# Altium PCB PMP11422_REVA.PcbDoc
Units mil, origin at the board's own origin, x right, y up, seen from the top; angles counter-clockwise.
Board outline 3100 x 1500 mil, 4 copper layers (Top Layer, Mid-Layer 1, Mid-Layer 2, Bottom Layer), stack 62 mil thick; 66 components, 31 nets, 197 pads, 23 vias.
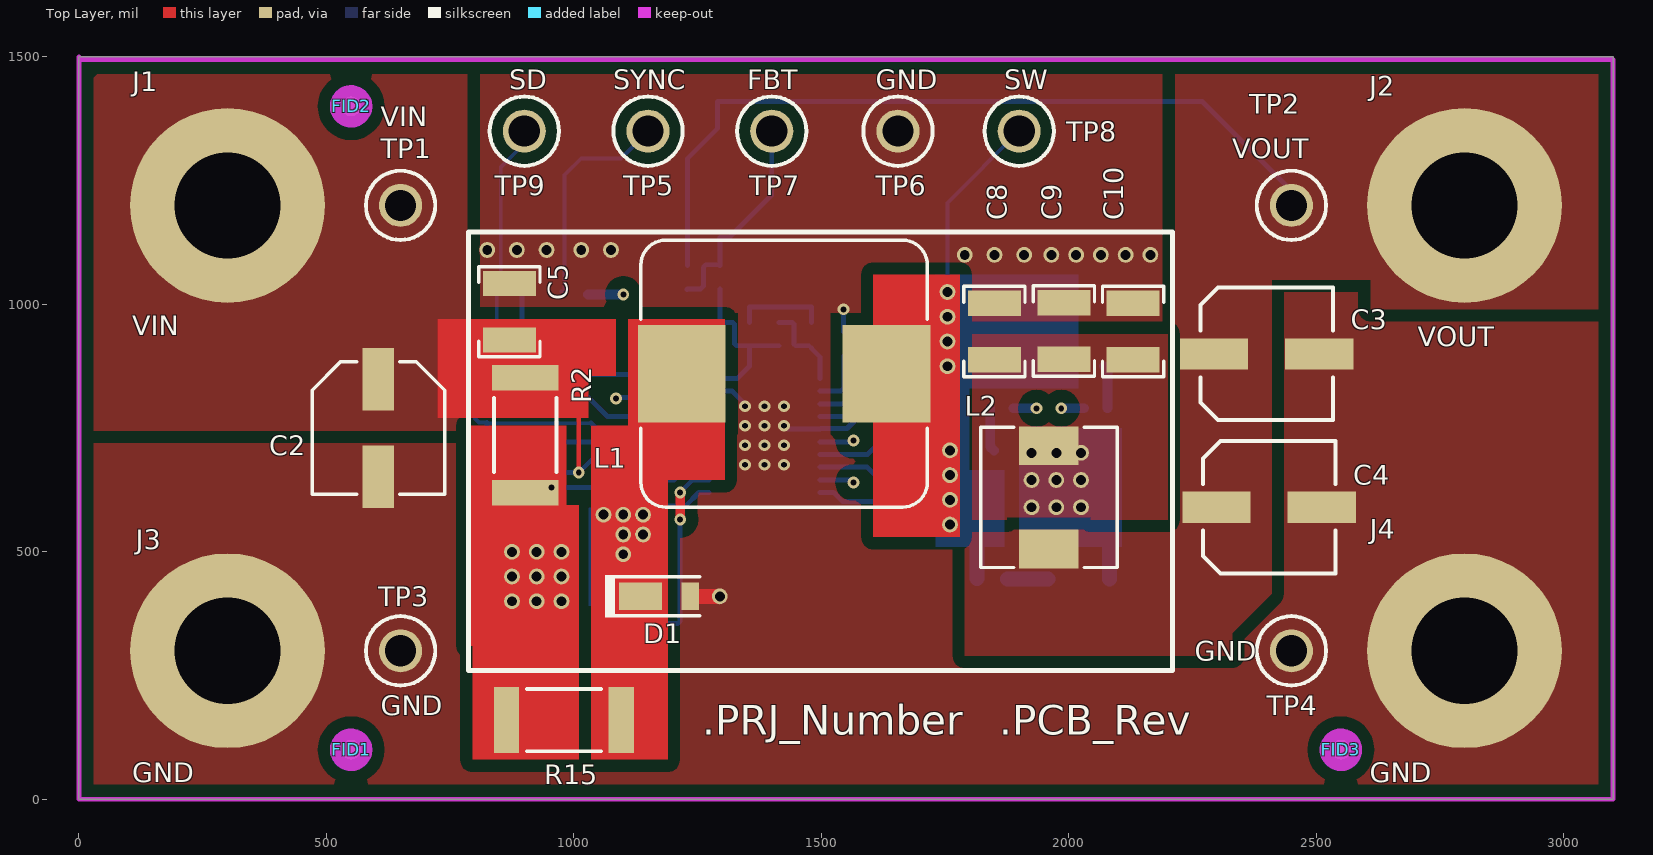
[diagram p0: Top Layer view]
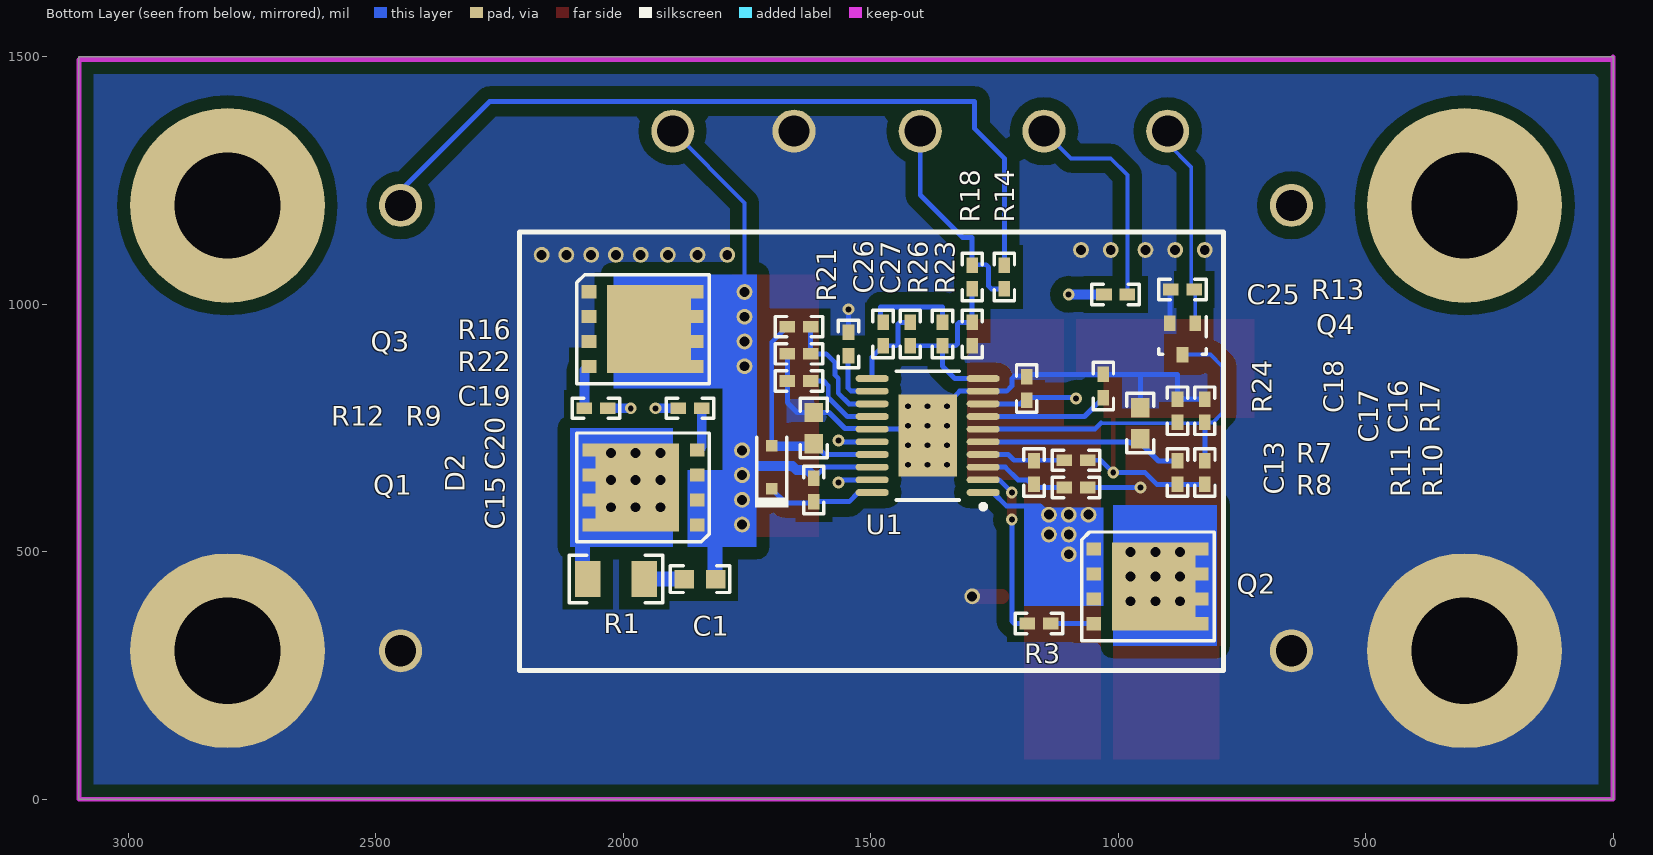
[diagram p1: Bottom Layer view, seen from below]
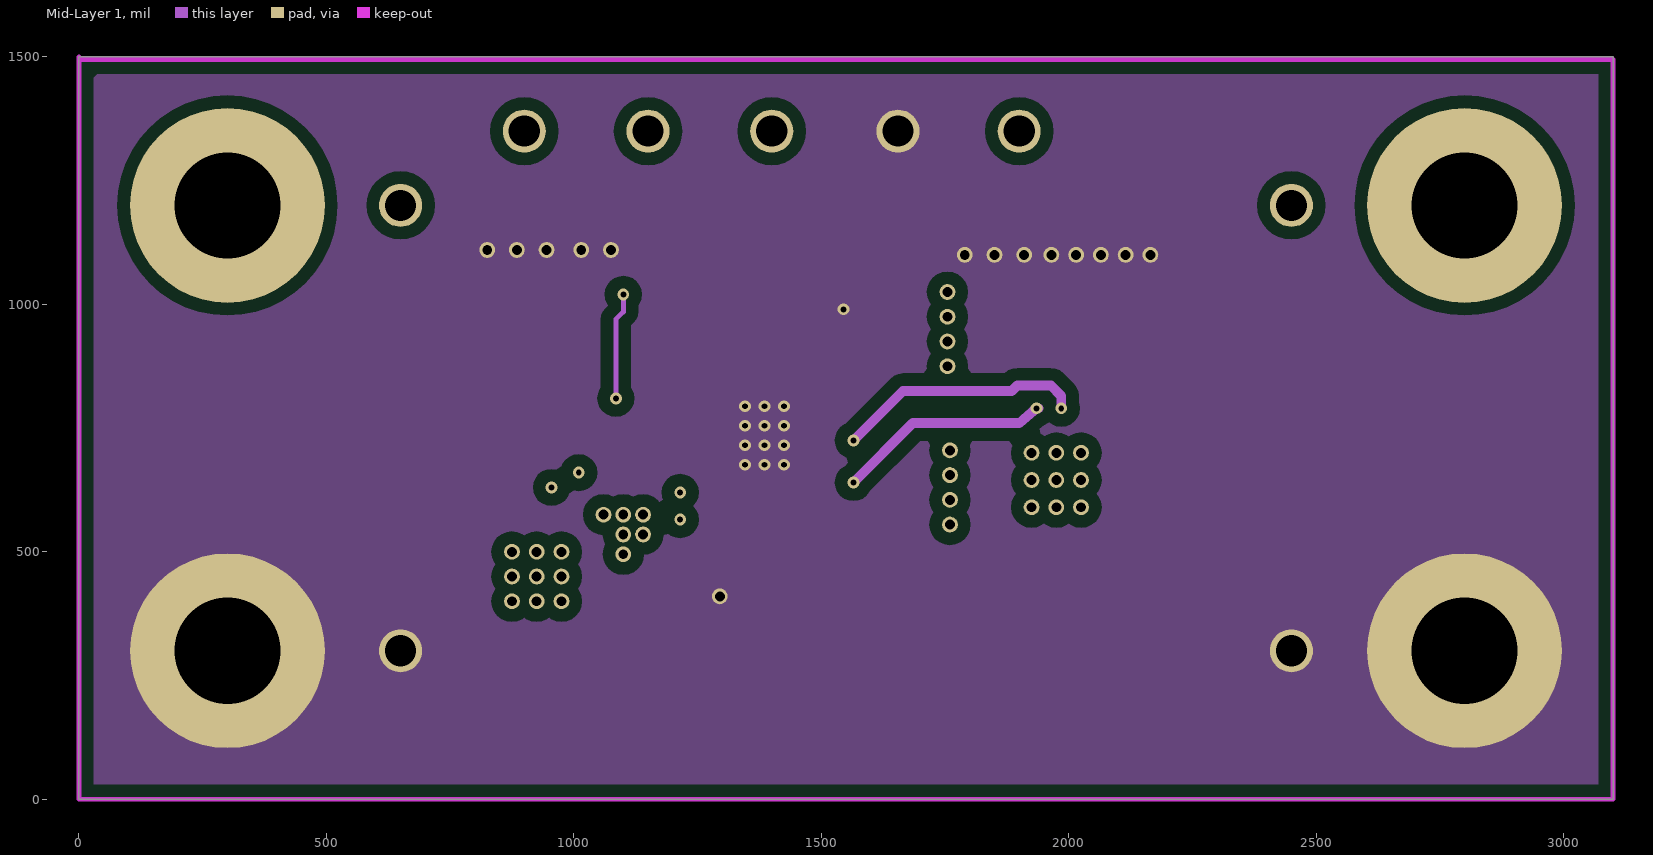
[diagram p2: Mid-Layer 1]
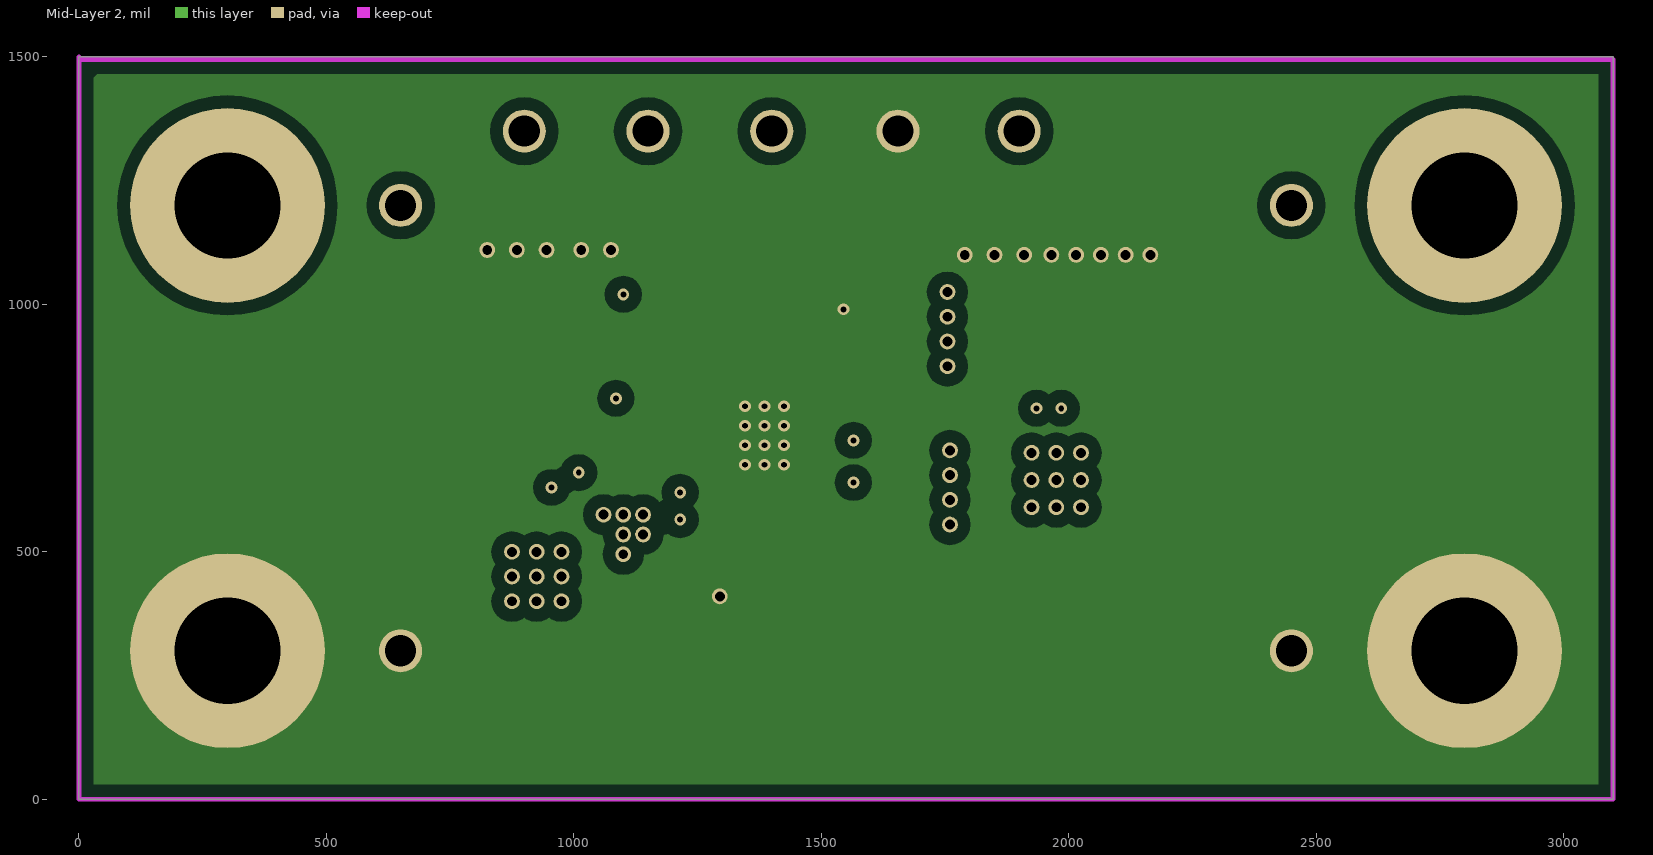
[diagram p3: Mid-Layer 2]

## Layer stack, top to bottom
Top Solder: solder mask 0.4, Solder Resist, Dk 3.5
Top Layer: signal copper 1.4
Dielectric1: core 12.6, FR-4, Dk 4.8
Mid-Layer 1: signal copper 0.7
Dielectric2: dielectric 32.6, FR-4, Dk 4.8
Mid-Layer 2: signal copper 0.7
Dielectric3: dielectric 12.6, FR-4, Dk 4.8
Bottom Layer: signal copper 1.4
Bottom Solder: solder mask 0.4, Solder Resist, Dk 3.5

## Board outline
0,0 3100,0 3100,1500 0,1500

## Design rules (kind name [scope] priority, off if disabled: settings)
AcuteAngle [All] p1: minimum=4.50000000000000E+0001 checktracksonly=FALSE
AssemblyTestPointUsage [All] p1: valid=2
Clearance Clearance_Keepouts [((IsTrack Or IsArc) And Not InPoly) And IsFree and IsKeepOut vs ((IsTrack Or IsArc) And Not InPoly) And IsFree and IsKeepOut] p1: gap=0
Clearance Clearance_BoardEdge_MountingHoles [OnCopper and InComponentClass('Mounting Holes') vs IsKeepOut] p2: gap=40
Clearance Clearance_BoardEdge_Poly [OnCopper and InPoly vs IsKeepOut] p3: gap=25
Clearance Clearance_BoardEdge [OnCopper and Not InComponentClass('Logo') and not InComponentClass('FiducialMark') and not InRegion(1000,500,4000,800) and Not IsKeepout vs IsKeepOut] p4: gap=75
Clearance Clearance_Poly [InPolygon] p5: gap=25
Clearance [All] p6: gap=7.87
ComponentClearance ComponentClearance_MountingHoles_FiducialMarks [InComponentClass('Mounting Holes') vs InComponentClass('FiducialMark')] p1: gap=50 collisioncheckmode=3 verticalgap=10 showdistances=FALSE
ComponentClearance ComponentClearance_Shunt [InComponentClass('Header') vs InComponentClass('Shunt')] p2: gap=0 collisioncheckmode=3 verticalgap=0 showdistances=FALSE
ComponentClearance ComponentClearance_Logo [InComponentClass('Logo')] p3: gap=50 collisioncheckmode=3 verticalgap=10 showdistances=FALSE
ComponentClearance ComponentClearance_ScrewToNut [(HasFootprint('NY PMS 440 0025 PH')) vs (HasFootprint('Keystone_1902C'))] p4: gap=5 collisioncheckmode=3 verticalgap=10 showdistances=FALSE
ComponentClearance ComponentClearance_MountingHoles [InComponentClass('Mounting Holes')] p5: gap=250 collisioncheckmode=3 verticalgap=100000 showdistances=FALSE
ComponentClearance ComponentClearance_SmallPassives [HasFootprint('0201*') or HasFootprint('0402*') or HasFootprint('0508') or HasFootprint('0603*') or HasFootprint('0612') or HasFootprint('0805*') or HasFootprint('0815*') or HasFootprint('0830*') or HasFootprint('1206*') or HasFootprint('1210*') or HasFootprint('1808*') or HasFootprint('1812*') or HasFootprint('1825*') or HasFootprint('2010*') or HasFootprint('2220*') or HasFootprint('2225*') or HasFootprint('2512*') or HasFootprint('2728*') or HasFootprint('3518*') vs HasFootprint('0201*') or HasFootprint('0402*') or HasFootprint('0508') or HasFootprint('0603*') or HasFootprint('0612') or HasFootprint('0805*') or HasFootprint('0815*') or HasFootprint('0830*') or HasFootprint('1206*') or HasFootprint('1210*') or HasFootprint('1808*') or HasFootprint('1812*') or HasFootprint('1825*') or HasFootprint('2010*') or HasFootprint('2220*') or HasFootprint('2225*') or HasFootprint('2512*') or HasFootprint('2728*') or HasFootprint('3518*')] p6: gap=20 collisioncheckmode=3 verticalgap=10 showdistances=FALSE
ComponentClearance ComponentClearance_THtoSMT [IsThruComponent vs IsSMTComponent] p7: gap=90 collisioncheckmode=3 verticalgap=30 showdistances=FALSE
ComponentClearance ComponentClearance_THtoTH [IsThruComponent vs IsThruComponent] p8: gap=118.11 collisioncheckmode=3 verticalgap=30 showdistances=FALSE
ComponentClearance [All] p9: gap=40 collisioncheckmode=3 verticalgap=10 showdistances=FALSE
DiffPairsRouting [All] p1: maxlimit=100 minlimit=10 mostfreqgap=10 toplayer_minwidth=15 toplayer_maxwidth=15 toplayer_prefwidth=15 midlayer1_minwidth=15 midlayer1_maxwidth=15 midlayer1_prefwidth=15 midlayer2_minwidth=15 midlayer2_maxwidth=15 midlayer2_prefwidth=15 bottomlayer_minwidth=15 bottomlayer_maxwidth=15 bottomlayer_prefwidth=15 maxuncoupledlength=1000
FabricationTestPointUsage TestPointUsage [All] p1: valid=2 allowmultiple=FALSE
FabricationTestpoint Testpoint [All] p1: side=3 testpointundercomponent=TRUE minsize=40 maxsize=100 preferedsize=60 minholesize=0 maxholesize=40 preferedholesize=32 testpointgrid=1 allowsidetop=TRUE allowsidebottom=TRUE usegrid=TRUE gridtolerance=0.01
FanoutControl Fanout_LCC [IsLCC] p1: bgadir=Out bgaviamode=Centered fanoutstyle=Auto fanoutdirection=Alternating viagrid=1 // Fanout_LCC (Default Rule)
FanoutControl Fanout_BGA [IsBGA] p2: bgadir=Out bgaviamode=Centered fanoutstyle=Auto fanoutdirection=Alternating viagrid=1 // Fanout_BGA (Default Rule)
FanoutControl Fanout_Default [All] p4: bgadir=Out bgaviamode=Centered fanoutstyle=Auto fanoutdirection=Alternating viagrid=1 // Fanout_Default (Default Rule)
FanoutControl Fanout_Small [(CompPinCount < 5)] p5: bgadir=Out bgaviamode=Centered fanoutstyle=Auto fanoutdirection=OutThenIn viagrid=1 // Fanout_Small (Default Rule)
HoleSize [All] p1: absolutevalues=TRUE maxlimit=251 minlimit=8 maxpercent=80.000 minpercent=20.000
MinimumAnnularRing MinimumAnnularRing_ThermalPadVias [IsVia and InAnyComponent] p1: minimumring=5.91
MinimumAnnularRing [All] p2: minimumring=6
MinimumSolderMaskSliver MinimumSolderMaskSliver_Logo [InComponentClass('Logo') vs InComponentClass('Logo')] p1: minsoldermaskwidth=0.7
MinimumSolderMaskSliver [All] p2: minsoldermaskwidth=4
PlaneConnect [All] p1: planeconnectstyle=Relief reliefexpansion=10 reliefentries=4 reliefconductorwidth=10 reliefairgap=10
PolygonConnect [All] p1: connectstyle=Direct reliefconductorwidth=10 reliefentries=4 polygonreliefangle="90 Angle" airgapwidth=10
RoutingVias ThermalPadVias [IsVia and InAnyComponent] p1: holewidth=7.87 width=19.68 viastyle="Through Hole" minholewidth=7.87 minwidth=19.68 maxholewidth=12.99 maxwidth=26
RoutingVias [All] p2: holewidth=16 width=34 viastyle="Through Hole" minholewidth=8 minwidth=20 maxholewidth=40 maxwidth=65
SilkToBoardRegionClearance [Not ((IsComment or IsDesignator) And (Hide <> 'False')) and not InRegion(1000,500,4000,800)] p1:
SilkToSilkClearance SilkToSilkClearance_Pb-FreeLogo [(HasFootprint('Pb-Free_Overlay_Medium') OR HasFootprint('Pb-Free_Overlay_Small')) vs (HasFootprint('Pb-Free_Overlay_Medium') OR HasFootprint('Pb-Free_Overlay_Small'))] p1: silktosilkclearance=0
SilkToSilkClearance [All] p2: silktosilkclearance=5
SilkToSolderMaskClearance SilkToComonentPadClearance [IsPad and InAnycomponent] p1: minsilkscreentomaskgap=5 clearancetoexposedcopper=TRUE
SilkToSolderMaskClearance "Silk to Solder Mask Opening" [All] p2: minsilkscreentomaskgap=4 clearancetoexposedcopper=FALSE
SolderMaskExpansion [All] p1: expansion=1.97
UnpouredPolygon [All] p1: allowunpoured=FALSE
Width [All] p1: maxlimit=100 minlimit=6 preferedwidth=10 checkconnectedcopper=TRUE
14 further rules are at their usual default settings.

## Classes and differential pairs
component class PMP11422_REVA_Hardware: FID1 FID2 FID3 ZZ2 ZZ3 ZZ4
component class FiducialMark: FID1 FID2 FID3
component class AssemblyNote: ZZ2 ZZ3 ZZ4
component class PMP11422_REVA: C1 C2 C3 C4 C5 C8 C9 C10 C13 C15 C16 C17 C18 C19 C20 C25 C26 C27 D1 D2 J1 J2 J3 J4 L1 L2 Q1 Q2 Q3 Q4 R1 R2 R3 R7 R8 R9 R10 R11 R12 R13 R14 R15 R16 R17 R18 R21 R22 R23 R24 R26 TP1 TP2 TP3 TP4 TP5 TP6 TP7 TP8 TP9 U1

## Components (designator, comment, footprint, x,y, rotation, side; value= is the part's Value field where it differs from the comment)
C1 "GRM188R72A331KA01D" 0603 1845,445 r180 bottom
C2 "EEE-FK1C101P" SM_RADIAL_D 605,750 r270 top
C3 "EMZJ160ADA151MF80G" MZJ_F80 2400,900 r0 top
C4 "EMZJ160ADA151MF80G" MZJ_F80 2405,590 r0 top
C5 "GRM32ER71E226KE15L" 1210 870,985 r90 top
C8 "GRM32ER71E226KE15L" 1210 1850,945 r90 top
C9 "GRM32ER71E226KE15L" 1210 1990.41,946.06 r90 top
C10 "GRM32ER71E226KE15L" 1210 2130,945 r90 top
C13 "GRM1555C1H101JA01D" 0402 1170,660 r90 bottom
C15 "GRM155R71C104KA88D" 0402 1615,625 r90 bottom
C16 "GRM1555C1H101JA01D" 0402 880,785 r90 bottom
C17 "GRM188R71C105KA12D" 0603 955,760 r90 bottom
C18 "GCM155R71H223KA55D" 0402 1030,835 r90 bottom
C19 "GRM155R71H472KA01D" 0402 1645,845 r0 bottom
C20 "GRM188R61C475KAAJ" 0603 1615,750 r90 bottom
C25 "GRM1555C1H101JA01D" 0402 1005,1020 r180 bottom
C26 "GCM155R71H223KA55D" 0402 1475,940 r90 bottom
C27 "GRM155R71H472KA01D" 0402 1420,940 r90 bottom
D1 "DFLS1100-7" powerDI123 1185,410 r0 top
D2 "BAT54WS-7-F" sod-323 1700,671.02 r90 bottom
FID1 "Fiducial" Fiducial10-20 550,100 r0 top
FID2 "Fiducial" Fiducial10-20 550,1400 r0 top
FID3 "Fiducial" Fiducial10-20 2550,100 r0 top
J1 "VIN" Keystone575-8 300,1200 r0 top
J2 "VOUT" Keystone575-8 2800,1200 r0 top
J3 "GND" Keystone575-8 300,300 r0 top
J4 "GND" Keystone575-8 2800,300 r0 top
L1 "7443551280" WE-HCA1 1425,860 r0 top
L2 "744302010" IND_WE-HCM_7050 1960,610 r270 top
Q1 "CSD16415Q5" TRANS_NexFET_Q5 1960,630 r0 bottom
Q2 "CSD16415Q5" TRANS_NexFET_Q5 940,430 r180 bottom
Q3 "CSD16415Q5" TRANS_NexFET_Q5 1960,950 r180 bottom
Q4 "2N7002KW" SOT-323 870,930 r270 bottom
R1 "CRCW120610R0JNEA" 1206 2015,445 r0 bottom
R2 "ERJ-M1WSF3M0U" 2512 901.65,735.79 r270 top
R3 "CRCW04020000Z0ED" 0402 1160,355 r0 bottom
R7 "CRCW0402100RJNED" 0402 1085,685 r180 bottom
R8 "CRCW0402100RJNED" 0402 1085,630 r180 bottom
R9 "CRCW04020000Z0ED" 0402 1865,790 r180 bottom
R10 "CRCW040225K5FKED" 0402 824.88,660 r270 bottom
R11 "CRCW04023R30JNED" 0402 880,660 r270 bottom
R12 "CRCW04020000Z0ED" 0402 2055,790 r0 bottom
R13 "CRCW0402100KJNED" 0402 870,1030 r180 bottom
R14 "CRCW040210R0FKED" 0402 1230,1055 r90 bottom
R15 "ERJ-M1WTF1M0U" 2512 980,160 r0 top
R16 "CRCW04020000Z0ED" 0402 1645,955 r180 bottom
R17 "CRCW04028K45FKED" 0402 825,785 r270 bottom
R18 "CRCW040215K4FKED" 0402 1295,1055 r90 bottom
R21 "CRCW0402267KFKED" 0402 1545,920 r270 bottom
R22 "DNP1" 0402 1645,900 r180 bottom
R23 "CRCW04021K69FKED" 0402 1295,940 r90 bottom
R24 "CRCW040230K0JNED" 0402 1185,830 r270 bottom
R26 "CRCW04028K06FKED" 0402 1355,940 r90 bottom
TP1 "VIN" Keystone5010 650,1200 r0 top
TP2 "VOUT" Keystone5010 2450,1200 r0 top
TP3 "GND" Keystone5011 650,300 r0 top
TP4 "GND" Keystone5011 2450,300 r0 top
TP5 "SYNC" Keystone5012 1150,1350 r0 top
TP6 "GND" Keystone5011 1655,1350 r0 top
TP7 "FBT" Keystone5012 1400,1350 r0 top
TP8 "SW" Keystone5012 1900,1350 r0 top
TP9 "SD" Keystone5012 900,1350 r0 top
U1 "LM5121MH/NOPB" PWP0020A_N 1385,735 r0 bottom
ZZ2 "These assemblies are ESD sensitive, ESD precautions shall be observed." AssemblyNote 185,3829.11 r0 top
ZZ3 "These assemblies must be clean and free from flux and all contaminants. Use of no clean flux is not acceptable." AssemblyNote 185,3740.56 r0 top
ZZ4 "These assemblies must comply with workmanship standards IPC-A-610 Class 2, unless otherwise specified." AssemblyNote 185,3652 r0 top

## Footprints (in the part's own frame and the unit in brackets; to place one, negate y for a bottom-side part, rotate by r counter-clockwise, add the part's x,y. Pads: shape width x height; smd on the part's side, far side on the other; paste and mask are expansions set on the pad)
0402 [mm] "0402 from SM-752 data"
  rect 0.8x0.6 smd: 1(-0.6,0) 2(0.6,0)
  silkscreen extent -1.22,-0.52 1.22,0.52, body extent -0.55,-0.3 0.55,0.3, height 0.6
0603 [mm] "0603 from SM-752 data"
  rect 1x0.95 smd: 1(-0.8,0) 2(0.8,0)
  silkscreen extent -1.52,-0.69 1.52,0.69, body extent -0.87,-0.47 0.87,0.47, height 0.85
1206 [mm] "1206 from SM-752 data"
  rect 1.3x1.85 smd: 1(-1.45,0) 2(1.45,0)
  silkscreen extent -2.4,-1.21 2.4,1.21, body extent -1.7,-0.9 1.7,0.9, height 1.35
1210 [mm] "1210 from SM-752 data"
  rect 1.3x2.7 smd: 1(-1.45,0) 2(1.45,0)
  silkscreen extent -2.32,-1.57 2.32,1.57, body extent -1.7,-1.35 1.7,1.35, height 1.35
2512 [mm] "Chip Resistor, Body 6.3x3.2mm, IPC Medium Density"
  rect 1.3x3.4 smd: 1(-2.95,0) 2(2.95,0)
  silkscreen extent -1.9,-1.6 1.9,1.6, body extent -3.22,-1.67 3.22,1.67, height 0.71
AssemblyNote [mil] "Assembly Note"
Fiducial10-20 [mm]
  round 1 smd mask+0.5: 1(0,0)
  Top Layer keep-out circle w1.178: c0,0 r0.5
IND_WE-HCM_7050 [mm] "WURTH ELEKTRONIK"
  rect 2x3.05 smd: 1(-2.65,0) 2(2.65,0)
  silkscreen extent -3.6,-3.5 3.6,3.5, body extent -3.57,-3.5 3.57,3.5, height 5
Keystone575-8 [mm] "Banana Jack"
  round 10 hole 5.45: 1(0,0)
  body extent -3.92,-3.94 3.95,3.94, height 2.36
Keystone5010 [mil] "Keystone Multipurpose loops"
  round 87 hole 63: 1(0,0)
  silkscreen extent -70,-70 70,70, body extent -63,-63 63,62, height 319
Keystone5011 [mil] "Keystone Multipurpose loops"
  round 87 hole 63: 1(0,0)
  silkscreen extent -70,-70 70,70, body extent -63,-63 63,62, height 319
Keystone5012 [mil] "Keystone Multipurpose loops"
  round 87 hole 63: 1(0,0)
  silkscreen extent -70,-70 70,70, body extent -63,-63 63,62, height 319
MZJ_F80 [mm] "SMD, 2-Leads, Dia 6.3mm"
  rect 3.5x1.6 smd: 1(-2.7,0) 2(2.7,0)
  silkscreen extent -3.4,-3.4 3.4,3.4, body extent -3.41,-3.41 3.41,3.41, height 8.01
powerDI123 [mm] "Diodes Inc recommended land pattern, document number DS30628 Rev. 6-2"
  rect 2.2x1.4 smd: 1(-1.275,0)
  rect 0.9x1.4 smd: 2(1.275,0)
  silkscreen extent -3.1,-1.09 1.76,1.09, body extent -2.38,-0.97 1.52,0.96, height 1
PWP0020A_N [mm] "TSOP, 20-Leads, Body 6.5x4.4mm, Pitch 0.65mm, Exposed Pad, IPC Medium Density"
  oval 1.7x0.35 smd: 1(-2.85,2.925) 2(-2.85,2.275) 3(-2.85,1.625) 4(-2.85,0.975) 5(-2.85,0.325) 6(-2.85,-0.325) 7(-2.85,-0.975) 8(-2.85,-1.625) 9(-2.85,-2.275) 10(-2.85,-2.925) 11(2.85,-2.925) 12(2.85,-2.275) 13(2.85,-1.625) 14(2.85,-0.975) 15(2.85,-0.325) 16(2.85,0.325) 17(2.85,0.975) 18(2.85,1.625) 19(2.85,2.275) 20(2.85,2.925)
  rect 3x4.2 smd: 21(0,0)
  silkscreen extent -2.97,-3.3 1.6,3.77, body extent -2.25,-3.3 2.25,3.3, height 1.1
SM_RADIAL_D [mm] "6.3 x 5.8mm:  Panasonic D"
  rect 3.2x1.6 smd: 1(-2.5,0) 2(2.5,0)
  silkscreen extent -3.4,-3.4 3.4,3.4, body extent -3.41,-3.41 3.41,3.41, height 6.1
sod-323 [mm] "NXP recommended land pattern"
  rect 0.6x0.6 smd paste-0.05: 1(-1.1,0) 2(1.1,0)
  silkscreen extent -2.06,-0.86 1.53,0.86, body extent -1.3,-0.67 1.3,0.68, height 1.1
SOT-323 [mm] "Zetex recommended land pattern.  March 2007"
  rect 0.8x0.6 smd: 1(-0.8,0.65) 2(-0.8,-0.65) 3(0.8,0)
  silkscreen extent -1.14,-1.22 0.77,1.22, body extent -1.13,-1.13 1.12,1.12, height 1.13
TRANS_NexFET_Q5 [mm] "TI recommended land pattern (nominal) M0139-01"
  rect 0.75x0.675 smd mask+0.051: 1(-2.776,1.917) 2(-2.776,0.639) 3(-2.776,-0.639) 4(-2.776,-1.917)
  rect 0.655x0.675 smd mask+0.051: 5(2.776,-1.917) 6(2.776,-0.639) 7(2.776,0.639) 8(2.776,1.917)
  rect 4.295x4.51 smd paste-2.2 mask+0.051: 9(0.301,0)
  silkscreen extent -3.4,-2.8 3.4,2.8, body extent -3.05,-2.55 3.05,2.55, height 1.06
WE-HCA1 [mm] "Wurth Electronik recommended land pattern"
  rect 4.5x5 smd: 1(-5.25,0) 2(5.25,0)
  silkscreen extent -7.35,-6.85 7.35,6.85, body extent -7.1,-6.68 7.12,6.64, height 6.5

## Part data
C1: "CAP, CERM, 330pF, 100V, +/-10%, X7R, 0603"
C2: "CAP, AL, 100 µF, 16 V, +/- 20%, 0.36 ohm, SMD"
C3 C4: "CAP, AL, 150 µF, 16 V, +/- 20%, 0.16 ohm, SMD"
C5 C8 C9 C10: "CAP, CERM, 22 µF, 25 V, +/- 10%, X7R, 1210"
C13: "CAP, CERM, 100pF, 50V, +/-5%, C0G/NP0, 0402"
C15: "CAP, CERM, 0.1uF, 16V, +/-10%, X7R, 0402"
C16 C25: "CAP, CERM, 100 pF, 50 V, +/- 5%, C0G/NP0, 0402"
C17: "CAP, CERM, 1 µF, 16 V, +/- 10%, X7R, 0603"
C18 C26: "CAP, CERM, 0.022 µF, 50 V, +/- 10%, C0G/NP0, 0402"
C19: "CAP, CERM, 4700pF, 50V, +/-10%, X7R, 0402"
C20: "CAP, CERM, 4.7 µF, 16 V, +/- 10%, X5R, 0603"
C27: "CAP, CERM, 4700 pF, 50 V, +/- 10%, X7R, 0402"
D1: "Diode, Schottky, 100V, 1A, PowerDI123"
D2: "Diode, Schottky, 30 V, 0.2 A, SOD-323"
FID1 FID2 FID3: "Fiducial mark.  There is nothing to buy or mount."
J1 J2 J3 J4: library part 575-8, "Standard Banana Jack, Uninsulated, 8.9mm"
L1: "Inductor, Shielded Drum Core, WE-Perm, 2.8 µH, 17.5 A, 0.0033 ohm, SMD"
L2: "Inductor, Shielded Drum Core, Ferrite, 105nH, 30A, 0.000235 ohm, SMD"
Q1 Q3: "MOSFET, N-CH, 25 V, 100 A, SON 5x6mm"
Q2: library part CSD16415q5, "MOSFET, N-CH, 25 V, 100 A, SON 5x6mm"
Q4: "MOSFET, N-CH, 60 V, 0.31 A, SOT-323"
R1: "RES, 10 ohm, 5%, 0.25W, 1206"
R2: "RES, 0.003, 1%, 1 W, 2512"
R3 R9 R12 R16: "RES, 0 ohm, 5%, 0.063W, 0402"
R7 R8: "RES, 100, 5%, 0.063 W, 0402"
R10: "RES, 25.5 k, 1%, 0.063 W, 0402"
R11: "RES, 3.3 ohm, 5%, 0.063W, 0402"
R13: "RES, 100 k, 5%, 0.063 W, 0402"
R14: "RES, 10.0 ohm, 1%, 0.063W, 0402"
R15: "RES, 0.001, 1%, 1 W, 2512"
R17: "RES, 8.45 k, 1%, 0.063 W, 0402"
R18: "RES, 15.4 k, 1%, 0.063 W, 0402"
R21: "RES, 267 k, 1%, 0.063 W, 0402"
R22: library part Resistor, "RES, xxx ohm, x%, xW, [PackageReference]"
R23: "RES, 1.69k ohm, 1%, 0.063W, 0402"
R24: "RES, 30 k, 5%, 0.063 W, 0402"
R26: "RES, 8.06 k, 1%, 0.063 W, 0402"
TP1 TP2: library part 5010, "Test Point, Multipurpose, Red, TH"
TP3 TP4 TP6: library part 5011, "Test Point, Multipurpose, Black, TH"
TP5 TP7 TP8 TP9: library part 5012, "Test Point, Multipurpose, White, TH"
U1: "Wide Input Synchronous Boost Controller with Disconnection Switch Control, PWP0020A"
ZZ2 ZZ3 ZZ4: library part AssemblyNote

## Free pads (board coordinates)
  round 32 hole 20: 0(825,1110) 0(875,400) 0(875,450) 0(875,500) 0(885,1110) 0(925,400) 0(925,450) 0(925,500) 0(945,1110) 0(975,400) 0(975,450) 0(975,500) 0(1015,1110) 0(1060,575) 0(1075,1110) 0(1100,495) 0(1100,535) 0(1100,575) 0(1140,535) 0(1140,575) 0(1295,410) 0(1755,875) 0(1755,925) 0(1755,975) 0(1755,1025) 0(1760,555) 0(1760,605) 0(1760,655) 0(1760,705) 0(1790,1100) 0(1850,1100) 0(1910,1100) 0(1925,590) 0(1925,645) 0(1925,700) 0(1965,1100) 0(1975,590) 0(1975,645) 0(1975,700) 0(2015,1100) 0(2025,590) 0(2025,645) 0(2025,700) 0(2065,1100) 0(2115,1100) 0(2165,1100)

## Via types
v1: diameter 24, hole 12, Top Layer to Bottom Layer, tented top, 16 vias
v2: diameter 24, hole 12, Top Layer to Bottom Layer, 7 vias

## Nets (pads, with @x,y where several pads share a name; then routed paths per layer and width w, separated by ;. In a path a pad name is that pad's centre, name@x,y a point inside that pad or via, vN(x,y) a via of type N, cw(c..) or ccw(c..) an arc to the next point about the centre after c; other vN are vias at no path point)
BST: C15.1 D2.1 U1.20 | length 222.9
  Bottom Layer w10: U1.20 1525.16,619.84 1543.62,601.38 C15.1 1617.38,599 1672.31,599 D2.1@1700,626.69
CMP: C26.2 R26.2 | length 187.8
  Bottom Layer w10: R26.2 1355,995 1480,995 C26.2@1480,963.62
COMP: C26.1 C27.2 U1.11 | length 171.3
  Bottom Layer w10: C27.2@1415,963.62 1441.38,963.62 1445,960 1445,920 1448.62,916.38 C26.1 ; C26.1@1480,911.38 1497.2,894.17 U1.11
CSN: C13.1 R8.1 U1.3 | length 176.2
  Bottom Layer w10: R8.1@1113.62,630 1168.62,630 1175,636.38 1183.62,645 1202,645 1228.02,671.02 U1.3
CSP: C13.2 R7.1 U1.4 | length 164
  Bottom Layer w10: R7.1@1113.62,685 1210.5,685 1222.11,696.61 U1.4
DG: R3.2 U1.2 | length 361.8
  Top Layer w20: v2(1215,565) v1(1215,620)
  Bottom Layer w10: R3.2 1210,355 1215,360 v2(1215,565) ; v1(1215,620) 1240.43,645.43 U1.2
DS: D1.1 L1.1 pad.0@1060,575 pad.0@1100,495 pad.0@1100,535 pad.0@1100,575 pad.0@1140,535 pad.0@1140,575 Q2.1 Q2.2 Q2.3 R15.2 U1.1 | length 262.1
  Top Layer w40: L1.1@1140,781.69 L1.1
  Bottom Layer w10: pad.0@1140,575 1158,593 1226.18,593 1253.03,619.84 U1.1
FB: C27.1 R18.1 R23.2 R26.1 U1.10 | length 364.7
  Bottom Layer w10: U1.10 1330.24,850.16 1355,874.92 R26.1 ; R18.1 R23.2 1321.38,963.62 1325,960 1325,920 1328.62,916.38 R26.1 ; C27.1@1415,916.38 R26.1
FBT: R14.1 R18.2 TP7.1 | length 433.4
  Bottom Layer w10: R14.1@1228.62,1030 R14.1 1256.38,1031.38 1261.81,1036.81 1261.81,1075 1266.81,1080 1293.62,1080 R18.2 ; R18.2@1295,1081.38 1295,1135 1314.17,1135 1400,1220.83 TP7.1
GND: C2.2 C3.2 C4.2 C5.2 C8.2 C9.2 C10.2 C16.2 C17.2 C18.2 C19.2 C20.2 D1.2 J3.1 J4.1 pad.0@825,1110 pad.0@885,1110 pad.0@945,1110 pad.0@1015,1110 pad.0@1075,1110 pad.0@1295,410 pad.0@1790,1100 pad.0@1850,1100 pad.0@1910,1100 pad.0@1965,1100 pad.0@2015,1100 pad.0@2065,1100 pad.0@2115,1100 pad.0@2165,1100 Q3.1 Q3.2 Q3.3 Q4.2 R13.1 R17.1 R21.1 R22.1 R23.1 R24.1 TP3.1 TP4.1 TP6.1 U1.9 U1.15 U1.21 | length 1213.4
  Top Layer w30: D1.2 pad.0@1295,410
  Bottom Layer w10: R17.1 C16.2 880,858.62 955,858.62 ; Q4.2 R13.1@895.59,1028.03 ; C17.2@955,800 955,858.62 ; R24.1 R24.1@1185,858.62 ; v1(1345.63,794.06) 1345.63,799.37 1320.43,824.57 U1.9 1225.43,824.57 1215,835 1215,850 1210,855 1188.62,855 R24.1@1185,858.62 ; v1(1424.37,754.69) 1431.26,747.8 U1.15 1498.61,749.21 1552.14,749.21 1584.43,781.5 C20.2 1648.5,781.5 1668.62,801.61 C19.2 R22.1 ; R21.1 v1(1545,990) ; 955,858.62 C18.2 R24.1@1185,858.62
  other v1: 1345.63,675.95 1385,675.95 1424.37,675.95 1345.63,715.32 1385,715.32 1424.37,715.32 1345.63,754.69 1385,754.69 1385,794.06 1424.37,794.06
HG: Q1.4 R9.2 | length 88.1
  Bottom Layer w20: R9.2 1841.38,712.4 Q1.4@1848.78,705
HO: R9.1 U1.19 | length 553.2
  Mid-Layer 1 w20: v1(1565,640) 1685,760 1900,760 v2(1935,790) ; v2(1935,790) 1939,790 v2(1935,790)
  Bottom Layer w10: U1.19 1564.57,645.43 v1@1565,645
  Bottom Layer w20: R9.1 v2(1935,790)
LG: Q3.4 R12.2 | length 88.1
  Bottom Layer w20: Q3.4@2071.22,875 2078.62,867.6 R12.2
LO: R12.1 U1.16 | length 615
  Mid-Layer 1 w20: v1(1565,725) 1665,825 1885,825 1896,836 1964,836 1985,815 v2(1985,790)
  Bottom Layer w10: U1.16 1562.2,722.21 v1(1565,725)
  Bottom Layer w20: v2(1985,790) R12.1
MODE: R16.2 R22.2 U1.13 | length 253.2
  Bottom Layer w10: U1.13 1543.98,798.98 1565.67,820.67 1565.67,850.67 1571.81,856.81 1571.81,881.81 1590,900 R22.2 R16.2
NetQ2_4: Q2.4 R3.1 | length 86.6
  Bottom Layer w10: Q2.4@1049.8,355 R3.1
NetQ4_1: Q4.1 R13.2 TP9.1 | length 408.7
  Bottom Layer w7.5: Q4.1 R13.2@844.41,1028.03 ; R13.2 852.62,1036.25 852.62,1277.62 900,1325 TP9.1
RES: C19.1 U1.14 | length 167.8
  Bottom Layer w10: U1.14 1547.29,773.39 1585.84,811.94 1585.84,835.84 1595,845 C19.1
RT: C25.1 R24.2 U1.8 | length 479.1
  Mid-Layer 1 w10: v2(1085,810) 1085,970 1100,985 v2(1100,1020)
  Bottom Layer w10: v2@1086.38,811.38 1185,811.38 1197.4,798.98 U1.8
  Bottom Layer w20: C25.1 v2(1100,1020)
SLOPE: R21.2 U1.12 | length 116.7
  Bottom Layer w10: U1.12 1539.57,824.57 1545.67,830.67 R21.2@1545.67,896.38
SNB: C1.1 R1.1 | length 81.4
  Bottom Layer w30: C1.1 R1.1
SS: C18.1 U1.7 | length 258.5
  Bottom Layer w10: C18.1 1067.99,773.39 U1.7
SW: C1.2 C15.2 L1.2 pad.0@1755,875 pad.0@1755,925 pad.0@1755,975 pad.0@1755,1025 pad.0@1760,555 pad.0@1760,605 pad.0@1760,655 pad.0@1760,705 Q1.1 Q1.2 Q1.3 Q3.5 Q3.6 Q3.7 Q3.8 Q3.9 TP8.1 U1.18 | length 803.9
  Bottom Layer w8: pad.0@1755,1025 1755,1205 TP8.1
  Bottom Layer w10: U1.18 1592.6,671.02 C15.2 ; 1736.02,671.02 1738,673
  Bottom Layer w20: C15.2 1615,652.5 1627.5,665 1650,665 1658,673 1738,673 1767,673
  Bottom Layer w30: 1813.5,519.72 Q1.1@1848.78,555 ; C1.2@1814.55,446 1814.55,520.72
SYNC: C25.2 TP5.1 | length 455.7
  Bottom Layer w8: C25.2@975,1026.38 C25.2 981.38,1261.38 1015,1295 1095,1295 TP5.1
UVLO: C16.1 Q4.3 R10.1 R17.2 U1.6 | length 757.9
  Bottom Layer w7.5: R17.2@825,760 1035,760 ; R17.2 808.62,761.38 790,780 790,875 813.5,898.5 Q4.3
  Bottom Layer w10: R10.1 R17.2@824.88,759.88 ; R17.2@825,760 R17.2 ; 1035,760 1047.2,747.8 U1.6
VCC: C20.1 D2.2 R16.1 U1.17 | length 471
  Bottom Layer w10: U1.17 1593.11,696.61 C20.1 ; C20.1@1617.32,718.5 C20.1 ; C20.1@1620.2,713.31 C20.1 ; R16.1 1700,923.62 D2.2@1700,713.31
  Bottom Layer w20: C20.1@1620.2,713.31 D2.2@1700,713.31
VIN: C2.1 C5.1 J1.1 R2.1 R7.2 R10.2 R11.2 TP1.1 | length 487.5
  Top Layer w10: 940,817.09 1007.91,817.09 1010,815 v2(1010,660)
  Bottom Layer w10: R10.2 R11.2 921.88,636.38 945.5,660 v2(1010,660) 1035,685 R7.2@1066.38,685
VIN1: C17.1 R11.1 U1.5 | length 388.8
  Bottom Layer w10: R11.1 918.62,683.62 955,720 975,720 977.2,722.21 U1.5@1252.8,722.21
VOP: C8.1 C9.1 C10.1 L2.1 pad.0@1925,590 pad.0@1925,645 pad.0@1925,700 pad.0@1975,590 pad.0@1975,645 pad.0@1975,700 pad.0@2025,590 pad.0@2025,645 pad.0@2025,700 Q1.5 Q1.6 Q1.7 Q1.8 Q1.9 R1.2 | length 224.6
  Bottom Layer w30: Q1.9@1986.57,630 2082.09,534.49 R1.2@2082.09,445
VOUT: C3.1 C4.1 J2.1 L2.2 R14.2 TP2.1 | length 1620.8
  Bottom Layer w10: R14.2 1230,1295 1290,1355 1290,1410 2270,1410 2450,1230 TP2.1
VR: pad.0@875,400 pad.0@875,450 pad.0@875,500 pad.0@925,400 pad.0@925,450 pad.0@925,500 pad.0@975,400 pad.0@975,450 pad.0@975,500 Q2.5 Q2.6 Q2.7 Q2.8 Q2.9 R2.2 R8.2 R15.1 | length 195.5
  Top Layer w10: 940,712.91 940,645 v2(955,630)
  Bottom Layer w10: v2(955,630) R8.2
pads on no net: FID1.1 FID2.1 FID3.1

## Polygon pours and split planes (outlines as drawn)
VOP on Top Layer "Top Layer-VOP" (solid, remove dead copper, pour order 47): 1785,940 1785,565 2200,565 2200,940 1785,940
GND on Top Layer "Top Layer-GND" (solid, remove dead copper, pour order 49): 0,1495 0,0 3100,0 3100,1485 3095,1490 3090,1495 0,1495
VIN on Top Layer "Top Layer-Vin" (solid, remove dead copper, pour order 46): 0,1495 0,745 785,745 785,1495 0,1495
VOUT on Top Layer "Top Layer-Vout" (solid, remove dead copper, pour order 48): 1790,550 1790,290 2330,290 2330,335 2405,410 2410,415 2410,1050 2610,1050 2610,990 3070,990 3070,1495 2215,1495 2215,550 1795,550
GND on Mid-Layer 1 "Top Layer-GND" (solid, remove dead copper, pour order 50): 0,1495 0,10 10,0 3100,0 3100,1495 3095,1500 5,1500
GND on Mid-Layer 2 "Mid-Layer 1-GND" (solid, remove dead copper, pour order 51): 0,1490 0,5 -5,0 3100,0 3100,1495 0,1495
GND on Bottom Layer "Mid-Layer 2-GND" (solid, remove dead copper, pour order 52): 0,1495 0,5 5,0 3100,0 3100,1495 0,1495

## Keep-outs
Keep-Out Layer:
  lines w10: 0,1495 3100,1495 3100,0 0,0 0,1500 ; 675,3900 ccw(c680,3900) 680,3895 ; 675,3900 ccw(c680,3900) 680,3895 ; 675,3900 ccw(c680,3900) 680,3895 ; 675,3900 ccw(c680,3900) 680,3895 ; 675,3900 ccw(c680,3900) 680,3895 ; 675,3900 ccw(c680,3900) 680,3895 ; 8130,3895 ccw(c8130,3900) 8135,3900 ; 8130,3895 ccw(c8130,3900) 8135,3900 ; 8130,3895 ccw(c8130,3900) 8135,3900 ; 8130,3895 ccw(c8130,3900) 8135,3900 ; 8130,3895 ccw(c8130,3900) 8135,3900 ; 8130,3895 ccw(c8130,3900) 8135,3900 ; 8130,7355 cw(c8130,7350) 8135,7350 ; 8130,7355 cw(c8130,7350) 8135,7350 ; 8130,7355 cw(c8130,7350) 8135,7350 ; 8130,7355 cw(c8130,7350) 8135,7350 ; 8130,7355 cw(c8130,7350) 8135,7350 ; 8130,7355 cw(c8130,7350) 8135,7350
  text ".Layer_Name" at 577,-858.49 h60

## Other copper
Top Layer:
  rectangle net VR: 795,80 1010,595
  rectangle net VR: 787.4,310 985,755
  rectangle net VIN: 725,770 1030,970
  rectangle net SW: 1605,530 1780,1060
  rectangle net VIN: 1020,855 1085,970
  rectangle net DS: 1110,645 1305,970
  rectangle net DS: 1035,80 1190,755
  text ".Layer_Name" at 577,-858.49 h60
Bottom Layer:
  rectangle net SW: 1730.5,510 1870,665
  rectangle net SW: 1730,640 1800,845
  rectangle net SW: 1730,830 2020,1059.98
  rectangle net VOP: 1900,510 2107.24,750
  rectangle net VR: 800,310 1010,595
  rectangle net DS: 1030,390 1190,590
  text ".Layer_Name" at 577,-858.49 h60

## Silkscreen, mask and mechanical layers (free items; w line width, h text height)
Top Overlay:
  lines w10: 787.4,260 2210,260 2210,1145.83 787.4,1145.83 787.4,261.97
  text ".PRJ_Number" at 1260,130 h60
  text ".PCB_Rev" at 1860,130 h60
  text ".Layer_Name" at 577,-858.49 h60
Bottom Overlay:
  lines w10: 787.4,260 2210,260 2210,1145.83 787.4,1145.83 787.4,261.97
  text ".Layer_Name" at 577,-858.49 h60
Top Paste:
  text ".Layer_Name" at 577,-858.49 h60
Bottom Paste:
  text ".Layer_Name" at 577,-858.49 h60
Top Solder:
  text ".Layer_Name" at 577,-858.49 h60
  text ".Layer_Name" at 577,-858.49 h60
Bottom Solder:
  text ".Layer_Name" at 577,-858.49 h60
Drill Guide:
  text ".Layer_Name" at 577,-858.49 h60
M1 Board Outline:
  the board outline again, w10
  text ".Layer_Name" at 577,-858.49 h60
M2 Board Dimensions:
  rectangle: 0,-275 125,-150
  rectangle: 125,-400 500,-275
  lines w7: 0,-275 1000,-275 ; 125,-400 125,-150 ; 250,-400 250,-150 ; 500,-400 500,-150 ; 750,-400 750,-150 ; 0,-400 1000,-400 1000,-150 0,-150 0,-400
  text ".Layer_Name" at 577,-858.49 h60
M3 3D STEP Top:
  text ".Layer_Name" at 577,-858.49 h60
M4 3D STEP Bottom:
  text ".Layer_Name" at 577,-858.49 h60
M5 Assembly Top:
  lines w10: -292,-930.17 6308,-930.17 ; -292,-726.83 6310,-726.83 ; -292,-523.5 -292,-1133.5 3713,-1133.5 6310,-1133.5 6310,-523.5 -291.5,-523.5 -291.5,-1133.5 1284,-1133.5 ; 2173,-1133.5 2173,-523.5 ; 3440,-726.83 3440,-523.5 ; 4280,-726.83 4280,-523.5 ; 4902,-1140 4902,-937.17
  text "COMPONENTS MARKED 'DNP' SHOULD NOT BE POPULATED." at 1153.5,-318.5 h60
  text "ASSEMBLY VARIANT:" at 1153,-434 h60
  text ".VariantName" at 2189,-434 h60
  text "PCB VIEWED FROM TOP SIDE" at -228.5,-655.67 h60
  text "BOARD #:" at 2248,-655.67 h60
  text ".PRJ_Number" at 2793.5,-655.67 h60
  text "REV:" at 3638,-655.67 h60
  text ".PCB_Rev" at 3929.5,-655.67 h60
  text "SVN REV:" at 4476,-655.67 h60
  text ".VersionControl_RevNumber" at 4982,-655.67 h60
  text "TID #:" at 2248,-859 h60
  text ".TID" at 2793.5,-859 h60
  text "PLOT NAME =" at -228.5,-1064.34 h60
  text ".plot_File_Name" at 577,-1064.34 h60
  text "GENERATED    :" at 2250,-1064.34 h60
  text ".Print_Date" at 3119.5,-1064.34 h60
  text ".Print_Time" at 3848.5,-1064.34 h60
  text "TEXAS INSTRUMENTS" at 5113,-1064.34 h60
M6 Assembly Bottom:
  lines w10: -292.5,-727.33 6309.5,-727.33 ; -290.5,-930.67 6309.5,-930.67 ; 1115.5,-1140.5 1115.5,-937.67 ; 1737.5,-727.33 1737.5,-524 ; 2577.5,-727.33 2577.5,-524 ; 3844.5,-1134 3844.5,-524 ; 4733.5,-1134 6309,-1134 6309,-524 -292.5,-524 -292.5,-1134 2304.5,-1134 6309.5,-1134 6309.5,-524
  text "COMPONENTS MARKED 'DNP' SHOULD NOT BE POPULATED." at 6102,-318 h60
  text ".VariantName" at 5058,-434 h60
  text "ASSEMBLY VARIANT:" at 6097,-434 h60
  text ".VersionControl_RevNumber" at 1035.5,-656.17 h60
  text "SVN REV:" at 1541.5,-656.17 h60
  text ".PCB_Rev" at 2088,-656.17 h60
  text "REV:" at 2379.5,-656.17 h60
  text ".PRJ_Number" at 3224,-656.17 h60
  text "BOARD #:" at 3769.5,-656.17 h60
  text "PCB VIEWED FROM BOTTOM SIDE" at 6246,-656.17 h60
  text ".TID" at 3224,-859.5 h60
  text "TID #:" at 3769.5,-859.5 h60
  text "TEXAS INSTRUMENTS" at 904.5,-1064.84 h60
  text ".Print_Time" at 2169,-1064.84 h60
  text ".Print_Date" at 2898,-1064.84 h60
  text "GENERATED    :" at 3767.5,-1064.84 h60
  text ".plot_File_Name" at 5440.5,-1064.84 h60
  text "PLOT NAME =" at 6246,-1064.84 h60
M9 Title Sheet:
  drawing of 57 lines, arcs and shapes, not listed
  text "1" at 739.84,8036.5 h70
  text "2" at 3235.5,8036.5 h70
  text "3" at 5724.84,8036.5 h70
  text "4" at 8231.51,8036.5 h70
  text "5" at 10730.5,8036.5 h70
  text "6" at 13235.5,8036.5 h70
  text "A" at -416.5,6893.5 h70
  text "A" at 14383.5,6893.5 h70
  text "B" at -416.5,4513.5 h70
  text "B" at 14383.5,4513.5 h70
  text "C" at -416.5,2138.5 h70
  text "C" at 14383.5,2138.5 h70
  text "PROJECT TITLE:" at 11343.5,277.5 h45
  text ".PRJ_Title" at 11393.5,144.17 h70
  text "DESIGNED FOR:" at 11343.5,-23.5 h45
  text ".PRJ_Customer" at 11393.5,-163.5 h70
  text "D" at -416.5,-231.5 h70
  text "D" at 14383.5,-231.5 h70
  text "FILE NAME:" at 11343.5,-323.5 h45
  text ".PCB_File_Name_No_Path" at 11393.5,-443.5 h70
  text "Texas Instruments (TI) and/or its licensors do not warrant the accuracy or completeness of this specification" at 6374,-605.34 h45
  text "ENGINEER:" at 11343.5,-613.5 h45
  text "LAYOUT BY:" at 12848.5,-613.5 h45
  text "or any information contained therein. TI and/or its licensors do not warrant that this design will meet" at 6329.01,-718 h45
  text ".PRJ_Engineer" at 11393.5,-768.49 h70
  text ".PCB_Layout" at 12899,-768.49 h70
  text "the specifications, will be suitable for your application or fit for any particular purpose, or will operate in" at 6329.01,-830.67 h45
  text ".Layer_Name" at 577,-858.49 h60
  text "ALTIUM DESIGNER VERSION:" at 12848.5,-923.5 h45
  text "an implementation. TI and/or its licensors do not warrant that the design is production worthy. You should" at 6329.01,-943.33 h45
  text "completely validate and test your design implementation to confirm the system functionality for your application." at 6374,-1056 h45
  text ".print_Scale" at 11393.5,-1056.83 h70
  text ".Application_BuildNumber" at 12899,-1056.83 h70
  text "1" at 739.84,-1263.5 h70
  text "2" at 3235.5,-1263.5 h70
  text "3" at 5724.84,-1263.5 h70
  text "4" at 8231.51,-1263.5 h70
  text "5" at 10730.5,-1263.5 h70
  text "6" at 13235.5,-1263.5 h70
M10 Fab Notes:
  drawing of 189 lines, arcs and shapes, not listed
  text "DESIGN INFORMATION" at 12381.02,6028 h60
  text "MIN. TRACK WIDTH:" at 11736.46,5848 h60
  text "8" at 12832.7,5848 h60
  text "MIL" at 12987.46,5848 h60
  text "MIN. CLEARANCE:" at 11736.46,5716 h60
  text "7.8" at 12772.7,5716 h60
  text "mm" at 12987.46,5716 h60
  text "MIN. VIA PAD SIZE:" at 11736.46,5584 h60
  text "20" at 12802.71,5584 h60
  text "MIL" at 12987.46,5584 h60
  text "0.05mm (2MIL)" at 12431.46,5442.29 h60
  text "MINIMUM ANNULAR RING" at 11407.23,5438 h60
  text "EXTERNAL" at 13139.46,5438 h60
  text "PER" at 11607.23,5320 h60
  text "IPC-D-275 CLASS 2 LEVEL C" at 11827.23,5320 h60
  text "MIL, HOLES" at 13315.46,5207.71 h60
  text "+/-" at 12923,5207 h60
  text "+/-" at 13777,5207 h60
  text "REGISTRATION TOLERANCES:" at 11407.23,5202 h60
  text "METAL" at 12607,5202 h60
  text "5" at 13183.2,5202 h60
  text "3" at 14016.2,5202 h60
  text "MIL" at 14132.46,5202 h60
  text "+/-" at 13777,5089 h60
  text "HOLE SIZE TOLERANCE (UNLESS OTHERWISE SPECIFIED):" at 11407.23,5084 h60
  text "3" at 14016.2,5084 h60
  text "MIL" at 14132.46,5084 h60
  text "MATERIAL:" at 11332.46,4874.54 h60
  text "FR-4" at 13775,4735 h60
  text "FR-4 High Tg" at 12318.9,4734.21 h60
  text "FR-408" at 11753.46,4725.64 h60
  text "OTHER" at 13241.46,4725.64 h60
  text "X" at 13055,4725 h60
  text "62 MIL (1.6mm) +/-10%" at 12073.56,4562.92 h60
  text "THICKNESS:" at 11407.23,4558.64 h60
  text "X" at 11945.4,4558.64 h60
  text "OTHER" at 13358.46,4558.64 h60
  text "TOLERANCE:" at 11407.23,4400.64 h60
  text "X" at 12246.53,4400.64 h60
  text "ANSI IPC-6012 TYPE 3 CLASS 2" at 12433.48,4400.64 h60
  text "OTHER +/-" at 12433.46,4244.64 h60
  text "BOW & TWIST:" at 11407.23,4087.64 h60
  text "X" at 12246.53,4087.64 h60
  text "ANSI IPC-6012 TYPE 3 CLASS 2" at 12433.48,4087.64 h60
  text "OTHER +/-" at 12433.46,3929.13 h60
  text "DRILLING:" at 11332.46,3790.64 h60
  text "REFERENCE:" at 11407.23,3673.64 h60
  text "X" at 12055.46,3673.64 h60
  text "AS SHOWN" at 12242.46,3673.64 h60
  text "X" at 12956.46,3673.64 h60
  text "NC_DRILL FILES" at 13093.46,3673.64 h60
  text "PTH MIN COPPER THICKNESS:" at 11407.23,3515.64 h60
  text "X" at 12757.46,3515.64 h60
  text "1MIL" at 12894.46,3515.64 h60
  text "OTHER" at 13391.46,3515.64 h60
  text "BOARD FINISH:" at 11332.46,3356.64 h60
  text "SILKSCREEN:" at 11487.68,3238.64 h60
  text "X" at 12436.46,3238.64 h60
  text "TOP" at 12562.46,3238.64 h60
  text "X" at 12946.46,3238.64 h60
  text "BOTTOM" at 13073.46,3238.64 h60
  text "SILKSCREEN COLOR:" at 11487.68,3071.64 h60
  text "X" at 12435.42,3071.64 h60
  text "WHITE" at 12562.46,3071.64 h60
  text "OTHER" at 13073.46,3071.64 h60
  text "X" at 12566.42,2912.44 h60
  text "GREEN" at 12693.46,2912.44 h60
  text "OTHER" at 13311.46,2912.44 h60
  text "SOLDER RESIST COLOR:" at 11487.68,2901.64 h60
  text "MATTE" at 12693.46,2742.44 h60
  text "SEMI-GLOSS" at 13311,2741.8 h60
  text "IMMERSION GOLD (ENIG)" at 12393.46,2553.92 h60
  text "ENEPIG" at 13731,2550.64 h60
  text "SURFACE FINISH:" at 11332.46,2549.64 h60
  text "HASL" at 13675,2410 h60
  text "IMM. TIN/SILVER OR EQUIV" at 11662,2392.64 h60
  text "OTHER" at 13093.46,2392.64 h60
  text "X" at 12915,2385 h60
  text "ARRAY/PANEL:" at 11332.46,2213.64 h60
  text "CUT AND TRIM PER M1 BOARD OUTLINE" at 12393.46,2209.35 h60
  text "X" at 12200,2205 h60
  text "N.C. ROUTE" at 12393.46,2057.64 h60
  text "V. SCORE" at 13259.46,2057.64 h60
  text "CERTIFICATION:" at 11332.46,1920.64 h60
  text "MATERIALS AND WORKMANSHIP FOR ALL PCBS" at 12057.46,1920.64 h60
  text "TO MEET OR EXCEED THE REQUIREMENTS OF:" at 12057.46,1822.64 h60
  text "X" at 11683.96,1686.13 h60
  text "ANSI IPC-A-600F CLASS ->" at 11822.96,1686.13 h60
  text "X" at 13462.02,1686.13 h60
  text "2" at 13580.96,1686.14 h60
  text "1" at 13265.96,1684.64 h60
  text "3" at 13934.96,1684.64 h60
  text "X" at 11686.02,1526.64 h60
  text "UL 94V-0" at 11822.96,1526.64 h60
  text "X" at 12498.02,1526.64 h60
  text "RoHS" at 12634.96,1526.64 h60
  text "OTHER" at 13279.36,1526.64 h60
  text "PER ORDER" at 13676.42,1526.64 h60
  text "ADDITIONAL REQUIREMENTS:" at 11332.46,1385.64 h60
  text "MICROSECTION:" at 11407.23,1270.64 h60
  text "YES" at 12312.96,1270.64 h60
  text "REQUIRED" at 13174.46,1114.49 h60
  text "BARE BOARD ELEC. TEST:" at 11407.23,1111.64 h60
  text "NONE" at 12712.96,1111.64 h60
  text "PER ORDER" at 13766.46,1111.64 h60
  text "X" at 13640,1110 h60
  text "MANUFACTURER'S UL:" at 11407.23,954.64 h60
  text "RAIL" at 12572.96,950.35 h60
  text "METAL" at 13064.77,950.35 h60
  text "X" at 13440,950 h60
  text "SILK" at 13576.46,950.35 h60
  text ".Layer_Name" at 577,-858.49 h60
M11 Gerber Information:
  lines w10: -292,-930.17 6308,-930.17 ; -292,-726.83 6310,-726.83 ; -292,-523.5 -292,-1133.5 3713,-1133.5 6310,-1133.5 6310,-523.5 -291.5,-523.5 -291.5,-1133.5 1284,-1133.5 ; 2173,-1133.5 2173,-523.5 ; 3440,-726.83 3440,-523.5 ; 4280,-726.83 4280,-523.5 ; 4902,-1140 4902,-937.17
  text "ALL ARTWORK VIEWED FROM TOP SIDE" at -228.5,-655.67 h60
  text "BOARD #:" at 2248,-655.67 h60
  text ".PRJ_Number" at 2793.5,-655.67 h60
  text "REV:" at 3638,-655.67 h60
  text ".PCB_Rev" at 3929.5,-655.67 h60
  text "SVN REV:" at 4476,-655.67 h60
  text ".VersionControl_RevNumber" at 4982,-655.67 h60
  text "LAYER NAME =" at -228.5,-858.49 h60
  text "TID #:" at 2248,-859 h60
  text ".TID" at 2793.5,-859 h60
  text "PLOT NAME =" at -228.5,-1064.34 h60
  text ".plot_File_Name" at 577,-1064.34 h60
  text "GENERATED    :" at 2250,-1064.34 h60
  text ".Print_Date" at 3119.5,-1064.34 h60
  text ".Print_Time" at 3848.5,-1064.34 h60
  text "TEXAS INSTRUMENTS" at 5113,-1064.34 h60
M12 Stackup:
  drawing of 411 lines, arcs and shapes, not listed
  text "Layer" at 5870,7606.2 h60
  text "Name" at 6279.91,7606.2 h60
  text "Material" at 7209.66,7606.2 h60
  text "Thickness" at 8069.42,7606.2 h60
  text "Constant" at 8719.26,7606.2 h60
  text "Board Layer Stack" at 9289.12,7606.2 h60
  text "1" at 5870,7486.2 h60
  text "Top Overlay" at 6279.91,7486.2 h60
  text "2" at 5870,7366.2 h60
  text "Top Solder" at 6279.91,7366.2 h60
  text "Solder Resist" at 7209.66,7366.2 h60
  text "0.40mil" at 8069.42,7366.2 h60
  text "3.5" at 8719.26,7366.2 h60
  text "3" at 5870,7246.2 h60
  text "Top Layer" at 6279.91,7246.2 h60
  text "Copper" at 7209.66,7246.2 h60
  text "1.40mil" at 8069.42,7246.2 h60
  text "4" at 5870,7126.2 h60
  text "Dielectric1" at 6279.91,7126.2 h60
  text "FR-4" at 7209.66,7126.2 h60
  text "12.60mil" at 8069.42,7126.2 h60
  text "4.8" at 8719.26,7126.2 h60
  text "5" at 5870,7006.2 h60
  text "Mid-Layer 1" at 6279.91,7006.2 h60
  text "Copper" at 7209.66,7006.2 h60
  text "0.70mil" at 8069.42,7006.2 h60
  text "6" at 5870,6886.2 h60
  text "Dielectric2" at 6279.91,6886.2 h60
  text "FR-4" at 7209.66,6886.2 h60
  text "32.60mil" at 8069.42,6886.2 h60
  text "4.8" at 8719.26,6886.2 h60
  text "7" at 5870,6766.2 h60
  text "Mid-Layer 2" at 6279.91,6766.2 h60
  text "Copper" at 7209.66,6766.2 h60
  text "0.70mil" at 8069.42,6766.2 h60
  text "8" at 5870,6646.2 h60
  text "Dielectric3" at 6279.91,6646.2 h60
  text "FR-4" at 7209.66,6646.2 h60
  text "12.60mil" at 8069.42,6646.2 h60
  text "4.8" at 8719.26,6646.2 h60
  text "9" at 5870,6526.2 h60
  text "Bottom Layer" at 6279.91,6526.2 h60
  text "Copper" at 7209.66,6526.2 h60
  text "1.40mil" at 8069.42,6526.2 h60
  text "10" at 5870,6406.2 h60
  text "Bottom Solder" at 6279.91,6406.2 h60
  text "Solder Resist" at 7209.66,6406.2 h60
  text "0.40mil" at 8069.42,6406.2 h60
  text "3.5" at 8719.26,6406.2 h60
  text "11" at 5870,6286.2 h60
  text "Bottom Overlay" at 6279.91,6286.2 h60
  text ".Layer_Name" at 577,-858.49 h60
M13 Component Bodies Top:
  text ".Layer_Name" at 577,-858.49 h60
M14 Component Bodies Bottom:
  text ".Layer_Name" at 577,-858.49 h60
M15 Courtyards Top:
  text ".Layer_Name" at 577,-858.49 h60
M16 Courtyards Bottom:
  text ".Layer_Name" at 577,-858.49 h60
Drill Drawing:
  circle w10: c5572.8,3220.83 r24.91
  lines w10: 5547.89,2772.45 5572.8,2747.54 5597.71,2772.45 5572.8,2797.36 5547.89,2772.45 ; 5547.89,2897 5572.8,2909.46 5597.71,2897 5585.26,2921.91 5597.71,2946.82 5572.8,2934.37 5547.89,2946.82 5560.35,2921.91 5547.89,2897 ; 5547.89,3096.28 5597.71,3096.28 5572.8,3046.46 5547.89,3096.28
  lines w12: 5480,2702.71 7599.4,2702.71 ; 5480,3300.54 7599.4,3300.54 ; 5850.67,2553.25 5850.67,3450 ; 6207.78,2553.25 6207.78,3450 ; 6869.79,2553.25 6869.79,3450 ; 7154.14,2553.25 7154.14,3450 ; 5480,2553.25 7599.4,2553.25 7599.4,3450 5480,3450 5480,2553.25
  text "Symbol" at 5569.68,3345.38 h72
  text "Quantity" at 5895.51,3345.38 h72
  text "Finished Hole Size" at 6252.62,3345.38 h72
  text "Plated" at 6914.62,3345.38 h72
  text "Hole Type" at 7198.98,3345.38 h72
  text "23" at 5895.51,3195.92 h60
  text "12.00mil (0.305mm)" at 6252.62,3195.92 h60
  text "PTH" at 6914.62,3195.92 h60
  text "Round" at 7198.98,3195.92 h60
  text "46" at 5895.51,3046.46 h60
  text "20.00mil (0.508mm)" at 6252.62,3046.46 h60
  text "PTH" at 6914.62,3046.46 h60
  text "Round" at 7198.98,3046.46 h60
  text "9" at 5895.51,2897 h60
  text "63.00mil (1.600mm)" at 6252.62,2897 h60
  text "PTH" at 6914.62,2897 h60
  text "Round" at 7198.98,2897 h60
  text "4" at 5895.51,2747.54 h60
  text "214.57mil (5.450mm)" at 6252.62,2747.54 h60
  text "PTH" at 6914.62,2747.54 h60
  text "Round" at 7198.98,2747.54 h60
  text "82 Total" at 5895.51,2598.09 h60
  text ".Layer_Name" at 577,-858.49 h60

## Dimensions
0,-400 to 1000,-400 on M2 Board Dimensions
0,0 to 0,1500 on M2 Board Dimensions
0,0 to 3100,0 on M2 Board Dimensions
